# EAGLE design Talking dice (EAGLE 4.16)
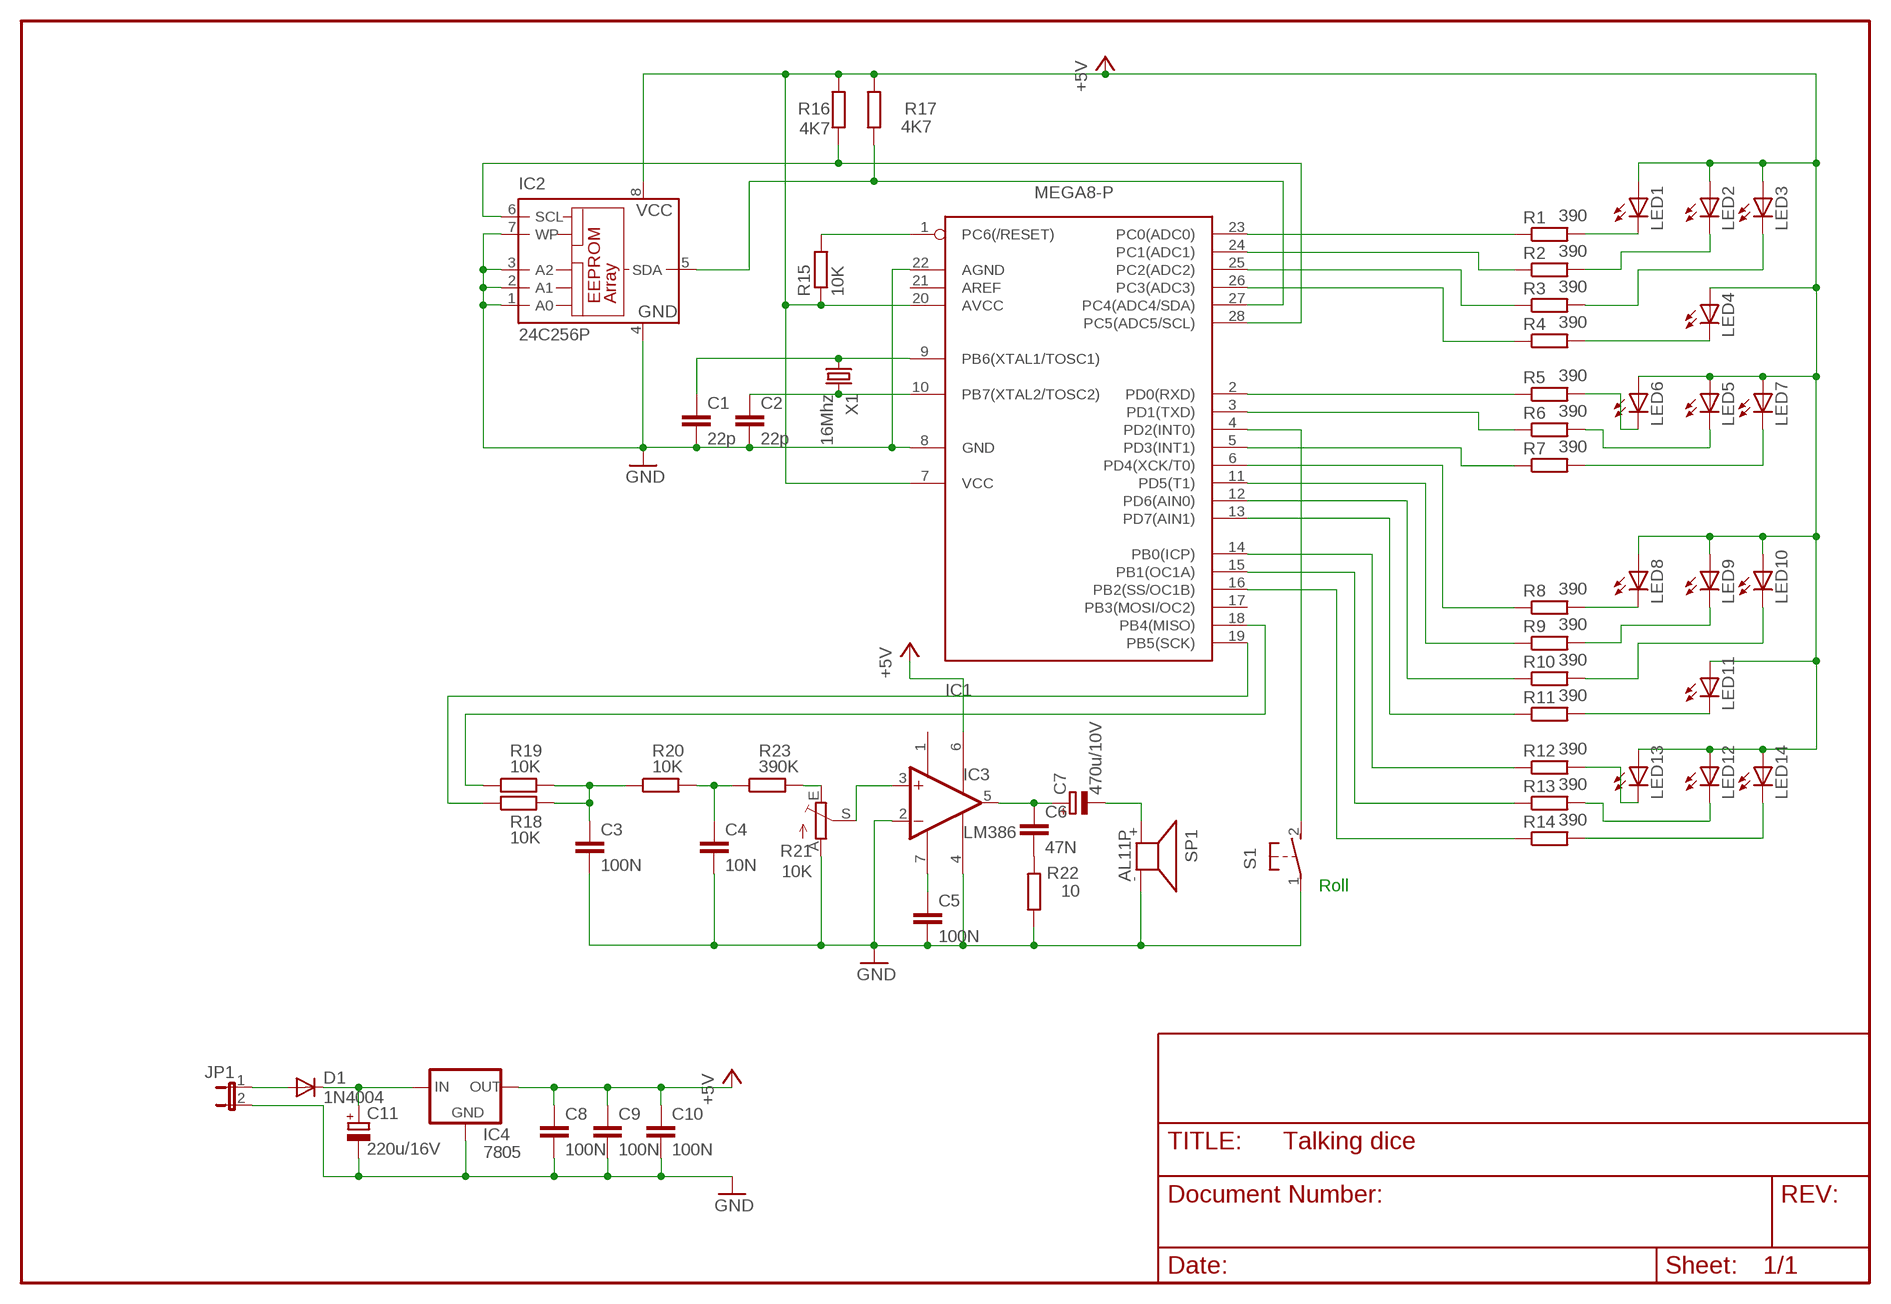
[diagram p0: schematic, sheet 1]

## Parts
C1  22p  C2.5/2  [C2.5-2]
C2  22p  C2.5/2  [C2.5-2]
C3  100N  C2.5/2  [C2.5-2]
C4  10N  C2.5/2  [C2.5-2]
C5  100N  C2.5/2  [C2.5-2]
C6  47N  C2.5/2  [C2.5-2]
C7  470u/10V  CPOL-EUE2,5-6E  [E2,5-6E]
C8  100N  C2.5/2  [C2.5-2]
C9  100N  C2.5/2  [C2.5-2]
C10  100N  C2.5/2  [C2.5-2]
C11  220u/16V  CPOL-EUE2.5-6  [E2,5-6]
D1  1N4004  [DO41-10]
IC1  MEGA8-P  [DIL28-3]
IC2  24C256P  [DIL8]
IC3  LM386  [DIL8]
IC4  7805  78XXS  [78XXS]
JP1  JP1E  [JP1]
LED1  LED5MM  [LED5MM]
LED2  LED5MM  [LED5MM]
LED3  LED5MM  [LED5MM]
LED4  LED5MM  [LED5MM]
LED5  LED5MM  [LED5MM]
LED6  LED5MM  [LED5MM]
LED7  LED5MM  [LED5MM]
LED8  LED5MM  [LED5MM]
LED9  LED5MM  [LED5MM]
LED10  LED5MM  [LED5MM]
LED11  LED5MM  [LED5MM]
LED12  LED5MM  [LED5MM]
LED13  LED5MM  [LED5MM]
LED14  LED5MM  [LED5MM]
R1  390  R-EU_0207/10  [0207/10]
R2  390  R-EU_0207/10  [0207/10]
R3  390  R-EU_0207/10  [0207/10]
R4  390  R-EU_0207/10  [0207/10]
R5  390  R-EU_0207/10  [0207/10]
R6  390  R-EU_0207/10  [0207/10]
R7  390  R-EU_0207/10  [0207/10]
R8  390  R-EU_0207/10  [0207/10]
R9  390  R-EU_0207/10  [0207/10]
R10  390  R-EU_0207/10  [0207/10]
R11  390  R-EU_0207/10  [0207/10]
R12  390  R-EU_0207/10  [0207/10]
R13  390  R-EU_0207/10  [0207/10]
R14  390  R-EU_0207/10  [0207/10]
R15  10K  R-EU_0207/10  [0207/10]
R16  4K7  R-EU_0207/10  [0207/10]
R17  4K7  R-EU_0207/10  [0207/10]
R18  10K  R-EU_0207/10  [0207/10]
R19  10K  R-EU_0207/10  [0207/10]
R20  10K  R-EU_0207/10  [0207/10]
R21  10K  TRIM_EU-ST15  [ST15]
R22  10  R-EU_0207/10  [0207/10]
R23  390K  R-EU_0207/10  [0207/10]
S1  31-XXPIN  [DRUK_PIN]
SP1  AL11P  [AL11P]
X1  16Mhz  CRYTALHC49U-V  [HC49U-V]

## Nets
+5V: C8.1 C9.1 C10.1 IC1.7(VCC) IC1.20(AVCC) IC2.8(VCC) IC3.6 IC4.OUT LED1.A LED2.A LED3.A LED4.A LED5.A LED6.A LED7.A LED8.A LED9.A LED10.A LED11.A LED12.A LED13.A LED14.A R15.1 R16.2 R17.2
GND: C1.2 C2.2 C3.2 C4.2 C5.2 C8.2 C9.2 C10.2 C11.- IC1.8(GND) IC1.22(AGND) IC2.1(A0) IC2.2(A1) IC2.3(A2) IC2.4(GND) IC2.7(WP) IC3.2(-IN) IC3.4 IC4.GND JP1.2 R21.A R22.1 S1.1(P) SP1.-
N$1: LED1.K(C) R1.2
N$2: LED2.K(C) R2.2
N$3: LED3.K(C) R3.2
N$4: C2.1 IC1.10(PB7(XTAL2/TOSC2)) X1.2
N$5: LED4.K(C) R4.2
N$6: IC1.2(PD0(RXD)) R5.1
N$7: LED5.K(C) R6.2
N$8: LED7.K(C) R7.2
N$9: LED6.K(C) R5.2
N$10: IC1.3(PD1(TXD)) R6.1
N$11: LED8.K(C) R8.2
N$12: LED9.K(C) R9.2
N$13: LED10.K(C) R10.2
N$14: C1.1 IC1.9(PB6(XTAL1/TOSC1)) X1.1
N$15: LED11.K(C) R11.2
N$16: LED12.K(C) R13.2
N$17: LED14.K(C) R14.2
N$18: LED13.K(C) R12.2
N$19: IC1.23(PC0(ADC0)) R1.1
N$20: IC1.24(PC1(ADC1)) R2.1
N$21: IC1.25(PC2(ADC2)) R3.1
N$22: IC1.26(PC3(ADC3)) R4.1
N$23: IC1.5(PD3(INT1)) R7.1
N$24: IC1.6(PD4(XCK/T0)) R8.1
N$25: IC1.11(PD5(T1)) R9.1
N$26: IC1.12(PD6(AIN0)) R10.1
N$27: IC1.13(PD7(AIN1)) R11.1
N$28: IC1.14(PB0(ICP)) R12.1
N$29: IC1.15(PB1(OC1A)) R13.1
N$30: IC1.16(PB2(SS/OC1B)) R14.1
N$31: IC1.1(PC6(/RESET)) R15.2
N$32: C3.1 R18.2 R19.2 R20.1
N$33: IC1.27(PC4(ADC4/SDA)) IC2.5(SDA) R17.1
N$34: IC1.28(PC5(ADC5/SCL)) IC2.6(SCL) R16.1
N$35: C4.1 R20.2 R23.1
N$36: IC3.3(+IN) R21.S
N$37: C6.2 R22.2
N$38: C6.1 C7.+ IC3.5(OUT)
N$39: C7.- SP1.+
N$40: IC1.19(PB5(SCK)) R18.1
N$41: IC1.18(PB4(MISO)) R19.1
N$42: C5.1 IC3.7
N$43: D1.A JP1.1
N$44: C11.+ D1.C IC4.IN
N$45: IC1.4(PD2(INT0)) S1.2(S)
N$46: R21.E R23.2
Unconnected: IC1.17(PB3(MOSI/OC2)) IC1.21(AREF) IC3.1

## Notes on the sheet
- Roll

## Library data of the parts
C1-C6 C8-C10 = capacitor-wima:C: CAPACITOR
C7 C11 = rcl:CPOL-EU: POLARIZED CAPACITOR, European symbol
D1 = diode:1N4004: DIODE
IC1 = avr:MEGA8-P: MICROCONTROLLER 8 Kbytes FLASH 1 kbytes SRAM 512 bytes EEPROM USART 4-channel 10 bit ADC 2-channel 8 bit ADC
IC2 = microchip:24C*: Serial EEPROM 1 K/2 K/4 K
IC3 = Evert:LM386: OP AMP
IC4 = v-reg:78XXS: VOLTAGE REGULATOR
JP1 = jumper:JP1E: JUMPER
LED1-LED14 = led:LED: LED
R1-R20 R22 R23 = rcl:R-EU_: RESISTOR, European symbol
R21 = pot:TRIM_EU-: POTENTIOMETER
S1 = Evert:31-XX: OMRON SWITCH
SP1 = Evert:AL11P: SPEAKER
X1 = crystal:CRYTAL: CRYSTAL

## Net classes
0 default: width 0.508 mm, drill 0.127 mm
1 Vcc: width 0.635 mm, drill 0.127 mm
2 Power: width 25 mm, drill 0.127 mm

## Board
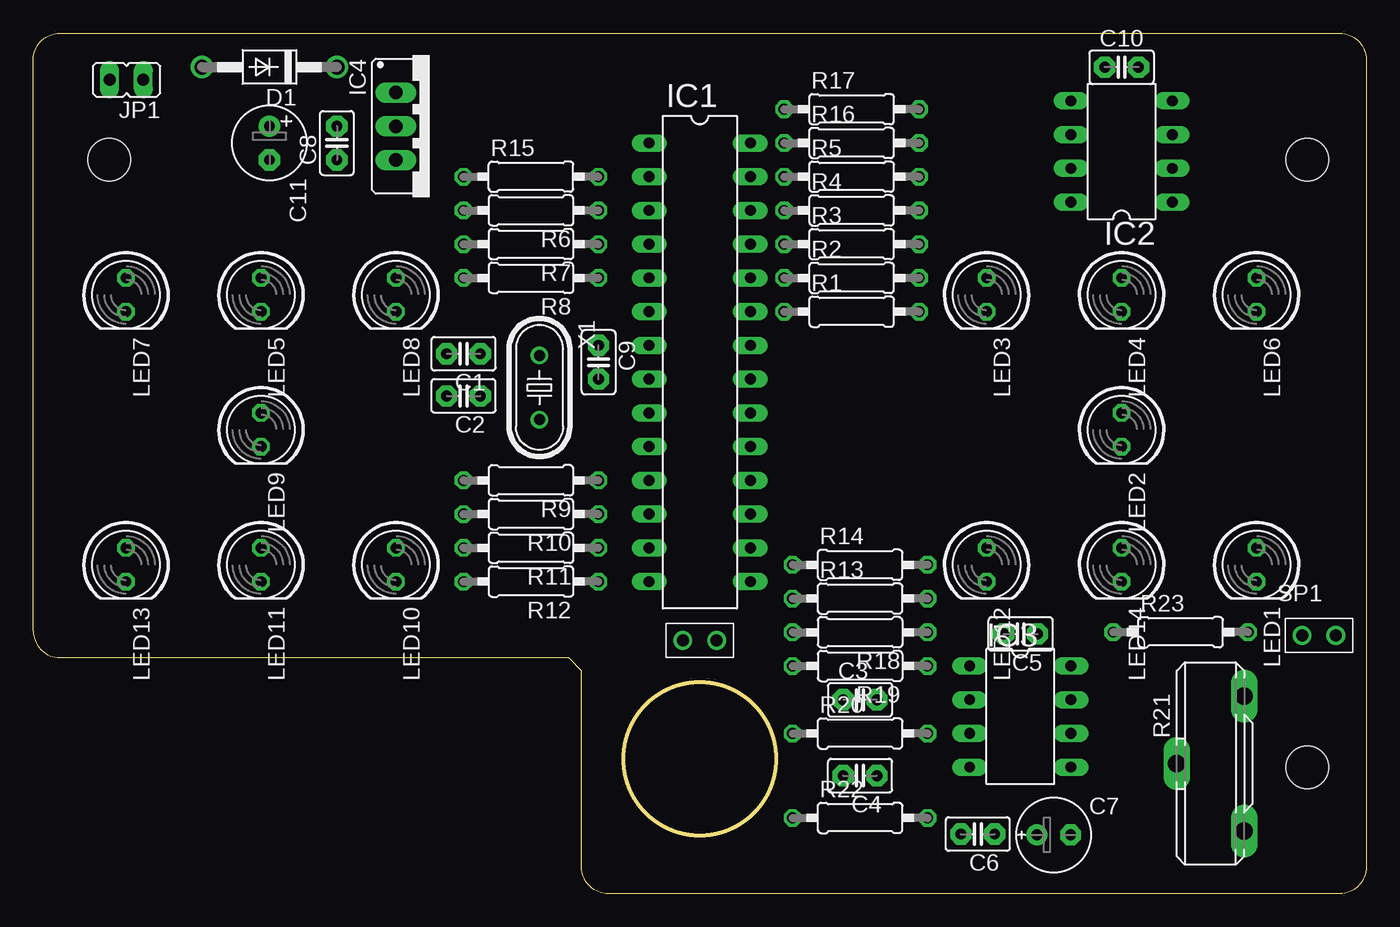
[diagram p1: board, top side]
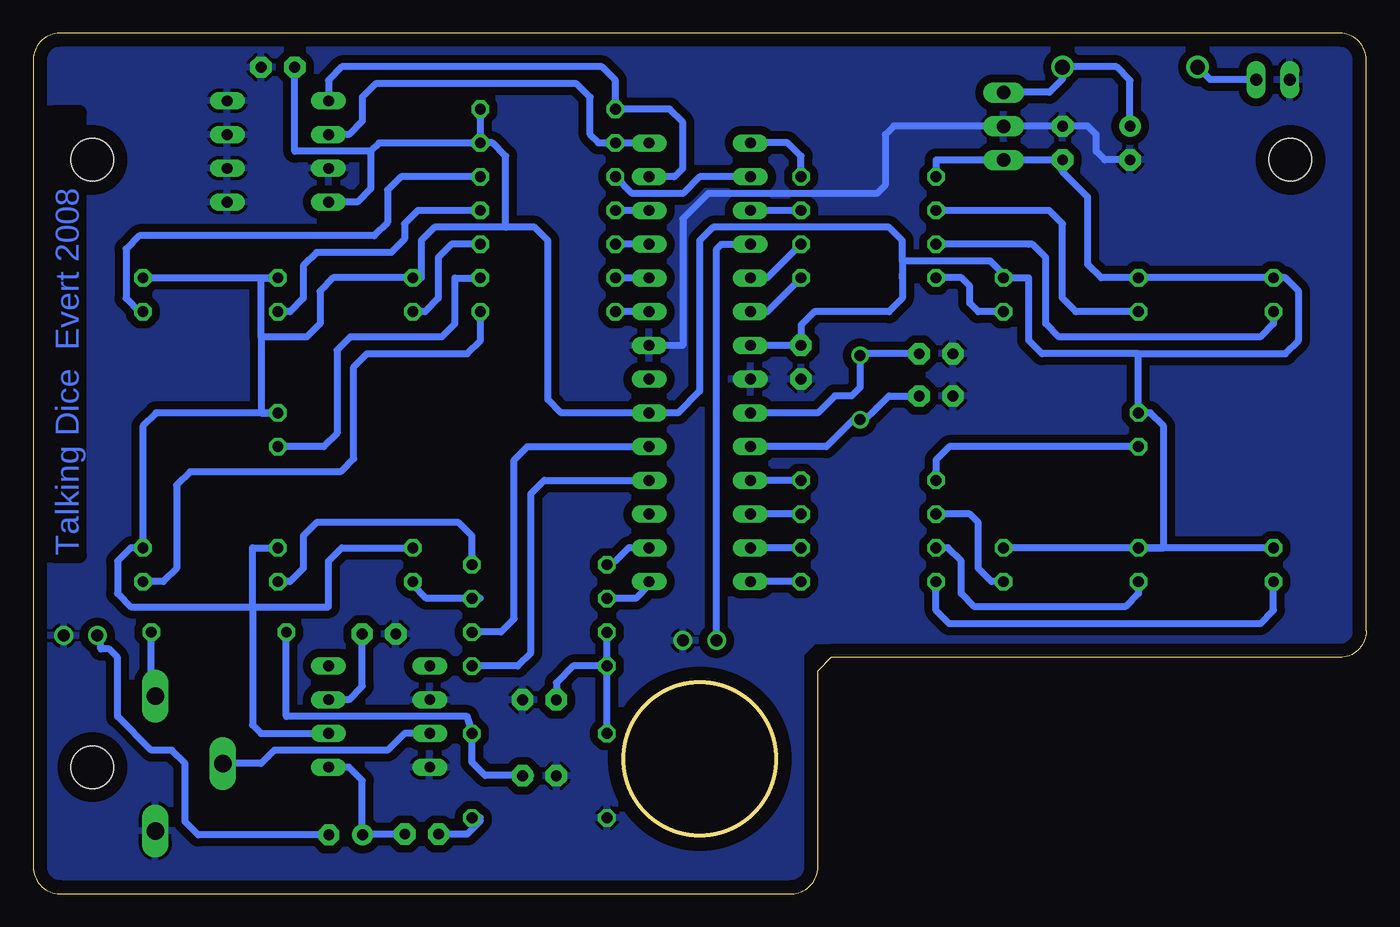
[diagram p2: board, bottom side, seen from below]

Size 100.33 x 64.77 mm. Coordinates in mm from the lower left corner, seen from the top.
Outline: 40.27,17.78 41.27,16.78 41.27,2 arc90 43.27,0 98.33,0 arc90 100.33,2 100.33,62.77 arc90 98.33,64.77 2,64.77 arc90 0,62.77 0,19.78 arc90 2,17.78 40.27,17.78
Outline: circle at 50.16,10.16 radius 5.75
Copper layers (1*16): Top 0.035mm / dielectric 1.5mm / Bottom 0.035mm
Design rules "default": minimum track width 10mil, minimum drill 24mil, track to track 8mil, track to pad 8mil, pad to pad 8mil, via to via 8mil, smd to smd 8mil, copper to edge 40mil, drill to drill 8mil, minimum pad ring 10mil, minimum via ring 8mil, stop-mask expansion 4mil, vias tented up to drill 0mil, thermal gap 10mil
Holes 3.2 mm at 5.71,55.24 95.89,9.52 95.89,55.24

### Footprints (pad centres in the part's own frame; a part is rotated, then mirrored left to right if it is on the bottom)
C2.5-2 = drill 0.813 pad 1.6 octagon: 1 -1.27,0; 2 1.27,0
E2,5-6E = drill 0.813 pad 1.575 round: + -1.27,0 | drill 0.813 pad 1.575 octagon: - 1.27,0
E2,5-6 = drill 0.813 pad 1.6 round: + -1.27,0 | drill 0.813 pad 1.6 octagon: - 1.27,0
DO41-10 = drill 1.118 round: A 5.08,0; C -5.08,0
DIL28-3 = drill 0.813 long: 1 -16.51,-3.81; 2 -13.97,-3.81; 3 -11.43,-3.81; 4 -8.89,-3.81; 5 -6.35,-3.81; 6 -3.81,-3.81; 7 -1.27,-3.81; 8 1.27,-3.81; 9 3.81,-3.81; 10 6.35,-3.81; 11 8.89,-3.81; 12 11.43,-3.81; 13 13.97,-3.81; 14 16.51,-3.81; 15 16.51,3.81; 16 13.97,3.81; 17 11.43,3.81; 18 8.89,3.81; 19 6.35,3.81; 20 3.81,3.81; 21 1.27,3.81; 22 -1.27,3.81; 23 -3.81,3.81; 24 -6.35,3.81; 25 -8.89,3.81; 26 -11.43,3.81; 27 -13.97,3.81; 28 -16.51,3.81
DIL8 = drill 0.813 long: 1 -3.81,-3.81; 2 -1.27,-3.81; 3 1.27,-3.81; 4 3.81,-3.81; 5 3.81,3.81; 6 1.27,3.81; 7 -1.27,3.81; 8 -3.81,3.81
78XXS = drill 1.016 long: GND 0,-2.54; IN -2.54,-2.54; OUT 2.54,-2.54
JP1 = drill 0.914 long: 1 0,-1.27; 2 0,1.27
LED5MM = drill 0.813 octagon: A -1.27,0; K 1.27,0
0207/10 = drill 0.813 octagon: 1 -5.08,0; 2 5.08,0
ST15 = drill 1.321 long: A -5.08,-2.54; E 5.08,-2.54; S 0,2.54
DRUK_PIN = drill 0.9 round: 1 -1.27,0; 2 1.27,0
AL11P = drill 0.9 round: + -1.27,0; - 1.27,0
HC49U-V = drill 0.813 round: 1 -2.413,0; 2 2.413,0

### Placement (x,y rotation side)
C1  32.38,40.64 180 top
C2  32.38,37.46 180 top
C3  62.23,14.6 0 top
C4  62.23,8.88 180 top
C5  74.31,19.55 180 top
C6  71.09,4.49 180 top
C7  76.81,4.42 0 top
C8  22.86,56.5 90 top
C9  42.54,40 270 top
C10  81.92,62.22 0 top
C11  17.78,56.5 270 top
D1  17.78,62.22 180 top
IC1  50.16,40 270 top
IC2  81.92,55.87 90 top
IC3  74.29,13.33 270 top
IC4  29.84,57.77 270 top
JP1  7.02,61.27 90 top
LED1  92.08,24.76 270 top
LED2  81.92,34.92 270 top
LED3  71.76,45.08 270 top
LED4  81.92,45.08 270 top
LED5  17.15,45.08 270 top
LED6  92.08,45.08 270 top
LED7  6.98,45.08 270 top
LED8  27.31,45.08 270 top
LED9  17.15,34.92 270 top
LED10  27.31,24.76 270 top
LED11  17.15,24.76 270 top
LED12  71.76,24.76 270 top
LED13  6.98,24.76 270 top
LED14  81.92,24.76 270 top
R1  61.59,43.81 0 top
R2  61.59,46.35 0 top
R3  61.59,48.89 0 top
R4  61.59,51.43 0 top
R5  61.59,53.97 0 top
R6  37.46,51.43 180 top
R7  37.46,48.89 180 top
R8  37.46,46.35 180 top
R9  37.46,31.11 180 top
R10  37.46,28.57 180 top
R11  37.46,26.03 180 top
R12  37.46,23.49 180 top
R13  62.23,22.21 0 top
R14  62.23,24.76 0 top
R15  37.46,53.97 0 top
R16  61.59,56.51 0 top
R17  61.59,59.05 0 top
R18  62.23,19.68 180 top
R19  62.23,17.14 180 top
R20  62.23,12.05 0 top
R21  88.59,9.8 90 top
R22  62.23,5.7 0 top
R23  86.36,19.69 0 top
S1  50.16,19.06 180 top
SP1  96.77,19.44 0 top
X1  38.1,38.1 270 top

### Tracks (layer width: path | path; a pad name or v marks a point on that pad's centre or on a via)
+5V
  Bottom 0.508: 17.15,40.64 24.4,40.64 25.4,41.64 25.4,46.33 25.43,46.35 LED8.A 27.31,46.62 28.31,47.62 34.92,47.62 | LED9.A 17.15,40.64 | LED11.A 15.24,26.04 15.24,35.19 16.24,36.19 LED9.A | LED10.A LED11.A | LED13.A LED11.A | 17.15,40.64 6.08,40.64 5.08,41.64 5.08,45.35 6.08,46.35 LED7.A | LED7.A | LED7.A LED5.A | 27.3,55.24 27.31,55.24 | IC4.OUT 27.3,55.24 | C8.1 IC4.OUT 27.3,55.24 | IC4.OUT 32.37,55.23 32.38,55.24 R15.1 | IC4.OUT C8.1 22.86,54.34 20.96,52.43 20.96,47.35 19.96,46.35 LED5.A | LED5.A | LED4.A LED6.A | LED4.A 83.19,46.35 83.19,41.91 | LED4.A 83.19,46.35 83.19,41.91 | 83.19,41.91 83.19,36.2 LED2.A 91.08,36.19 92.08,35.19 LED1.A 92.98,26.03 93.98,25.03 93.98,22.59 92.98,21.59 83.82,21.59 | 83.82,21.59 83.82,26.04 LED14.A 83.82,26.03 83.82,21.59 | 83.82,21.59 78.11,21.59 78.11,25.04 77.11,26.04 LED12.A | R16.2 R17.2 | 74.93,55.88 74.3,56.51 R16.2 | IC2.8 78.11,52.07 75.93,52.07 74.93,53.07 74.93,55.88 | C10.1 80.65,55.88 74.93,55.88 | 64.77,50.16 70.12,50.16 71.12,49.16 71.12,46.35 LED3.A 77.74,46.35 78.74,45.35 78.74,42.91 79.74,41.91 83.19,41.91 | 64.77,50.16 64.77,55.52 65.77,56.52 R16.2 | 64.77,50.16 62.59,50.16 61.59,49.16 61.59,37.19 60.59,36.19 IC1.20 51.8,36.19 50.16,37.82 50.16,49.16 49.16,50.16 35.92,50.16 34.92,49.16 34.92,47.62 | 34.92,46.35 34.92,46.62 | 34.92,46.35 34.92,44.81 35.92,43.81 41.54,43.81 42.54,42.81 C9.1 IC1.7 | LED9.A | 34.92,47.62 34.92,46.35 | 83.82,21.59 83.82,12.7 83.19,12.06 IC3.6
GND
  Bottom 0.508: 27.3,57.78 IC4.GND C8.2 20.96,57.78 20.32,57.15 20.32,55.88 19.69,55.24 C11.- | 27.31,57.78 IC4.GND 27.3,57.78 | IC1.22 51.44,41.27 51.43,41.27 51.43,50.8 49.53,52.7 36.83,52.7 36.2,53.34 36.2,57.15 35.56,57.78 27.31,57.78 | 27.3,57.78 27.31,57.78
  pour Bottom (isolate 0.61): 98.7,64.14 99.7,63.13 99.7,1.64 98.7,0.64 44.18,0.64 42.54,1.64 42.54,18.05 41.54,19.05 1.64,19.05 0.64,20.05 0.64,63.13 1.64,64.14
N$1
  Bottom 0.508: R1.2 66.68,41.64 67.68,40.64 75.2,40.64 76.2,39.64 76.2,32.75 77.2,31.75 88.54,31.75 89.54,30.75 89.54,24.5 90.54,23.5 LED1.K
N$2
  Bottom 0.508: R2.2 68.58,46.35 68.58,42.91 69.58,41.91 76.47,41.91 77.47,40.91 77.47,34.66 78.47,33.66 LED2.K
N$3
  Bottom 0.508: LED3.K 70.85,43.81 69.85,44.81 69.85,47.89 68.85,48.89 R3.2
N$4
  Bottom 0.406: 38.1,35.56 X1.2 38.61,35.69 | IC1.10
  Bottom 0.508: 38.1,35.56 37.83,35.56 36.83,36.56 35.92,37.46 C2.1 | 38.61,35.69 40,34.29 40.64,33.66 IC1.10
N$5
  Bottom 0.508: R4.2 71.39,51.43 72.39,50.43 72.39,49.26 73.39,48.26 79.01,48.26 80.01,47.26 80.01,44.81 81.01,43.81 LED4.K
N$6
  Bottom 0.508: IC1.2 50.17,53.97 51.43,52.7 55.24,52.7 R5.1
N$7
  Bottom 0.508: R6.2 24.14,51.43 23.86,51.43 22.86,50.43 22.86,44.81 21.86,43.81 LED5.K
N$8
  Bottom 0.508: R7.2 25.41,48.89 25.13,48.89 24.13,47.89 24.13,42.91 23.13,41.91 7.98,41.91 6.98,42.91 LED7.K
N$9
  Bottom 0.508: R5.2 72.66,53.97 73.66,52.97 73.66,50.53 74.66,49.53 92.34,49.53 93.34,48.53 93.34,44.81 92.34,43.81 LED6.K
N$10
  Bottom 0.508: R6.1 42.71,51.43 | 42.71,51.43 IC1.3 | 42.71,51.43 42.71,51.63
N$11
  Bottom 0.508: LED8.K 29.21,43.81 29.85,44.45 29.85,45.72 30.48,46.35 R8.2
N$12
  Bottom 0.508: LED9.K 31.39,33.65 32.38,32.65 R9.2
N$13
  Bottom 0.508: R10.2 29.85,28.57 29.21,27.94 29.21,24.5 28.21,23.5 LED10.K
N$14
  Bottom 0.406: 38.1,40.64 X1.1 | IC1.9
  Bottom 0.508: C1.1 38.1,40.64 | X1.1 38.1,38.1 38.73,37.46 40,37.46 41.27,36.2 IC1.9
N$15
  Bottom 0.508: LED11.K 17.15,22.59 18.15,21.59 29.48,21.59 30.48,22.59 30.48,25.03 31.48,26.03 R11.2
N$16
  Bottom 0.508: R13.2 66.68,22.23 70.76,22.23 71.76,23.23 LED12.K
N$17
  Bottom 0.508: R14.2 67.31,26.94 68.31,27.94 79.01,27.94 80.01,26.94 80.01,24.5 81.01,23.5 LED14.K
N$18
  Bottom 0.508: LED13.K 6.98,21.32 7.98,20.32 31.39,20.32 32.38,21.32 R12.2
N$19
  Bottom 0.508: IC1.23 R1.1
N$20
  Bottom 0.508: IC1.24 R2.1
N$21
  Bottom 0.508: IC1.25 R3.1
N$22
  Bottom 0.508: IC1.26 R4.1
N$23
  Bottom 0.508: R7.1 42.71,48.89 | 42.71,48.89 42.71,49.09 | 42.71,48.89 42.71,48.73 45.09,46.35 IC1.5
N$24
  Bottom 0.508: R8.1 42.71,46.35 | 42.71,46.35 42.71,46.53 | 42.71,46.35 42.71,46.19 45.09,43.81 IC1.6
N$25
  Bottom 0.508: R9.1 IC1.11
N$26
  Bottom 0.508: R10.1 IC1.12
N$27
  Bottom 0.508: R11.1 IC1.13
N$28
  Bottom 0.508: IC1.14 R12.1
N$29
  Bottom 0.508: R13.1 56.52,22.23 54.98,22.23 53.98,23.23 IC1.15
N$30
  Bottom 0.508: IC1.16 55.52,26.03 56.52,25.03 R14.1
N$31
  Bottom 0.508: IC1.1 43.54,56.52 42.54,55.52 R15.2
N$32
  Bottom 0.508: R20.1 R19.2 | R19.2 R18.2 | R19.2 59.7,17.14 60.96,15.88 C3.1
N$33
  Bottom 0.508: IC2.5 78.11,61.23 77.11,62.23 57.52,62.23 56.52,61.23 R17.1 52.43,59.05 51.43,58.05 51.43,54.61 52.07,53.97 IC1.27
N$34
  Bottom 0.508: IC1.28 R16.1 57.78,56.51 57.78,56.52 58.42,57.15 58.42,59.96 59.42,60.96 74.57,60.96 75.57,59.96 75.57,58.15 76.57,57.15 78.11,57.15 IC2.6
N$35
  Bottom 0.508: C4.1 62.86,8.89 66.31,8.89 67.31,9.89 R20.2 67.31,12.33 67.68,13.33 81.28,13.33 R23.1
N$36
  Bottom 0.508: R21.S 83.19,9.8 82.19,10.79 73.66,10.79 72.39,12.06 IC3.3
N$37
  Bottom 0.508: 66.68,5.71 R22.2 66.68,5.48 67.68,4.49 C6.2
N$38
  Bottom 0.508: C6.1 75.57,4.49 75.57,4.42 | 75.57,4.42 C7.+ | IC3.5 76.57,9.53 75.57,8.53 75.57,4.42
N$39
  Bottom 0.508: C7.- 87.9,4.42 88.9,5.42 88.9,9.79 89.9,10.79 91.44,10.79 93.98,13.33 93.98,17.78 94.62,18.42 95.25,18.42 95.25,19.69 SP1.+
N$40
  Bottom 0.508: R18.1 66.68,19.69 65.14,19.69 64.14,20.69 64.14,32.65 63.13,33.65 IC1.19
N$41
  Bottom 0.508: R19.1 63.86,17.14 62.86,18.14 62.86,30.12 61.86,31.12 IC1.18
N$42
  Bottom 0.508: C5.1 75.57,19.55 75.57,15.61 76.57,14.61 IC3.7
N$43
  Bottom 0.508: D1.A | D1.A | JP1.1 11.75,61.27 D1.A
N$44
  Bottom 0.508: C11.+ 17.78,61.23 18.78,62.23 D1.C | D1.C | IC4.IN 27.31,60.32 23.86,60.32 22.86,61.32 D1.C
N$45
  Bottom 0.508: IC1.4 48.53,48.89 48.89,48.52 S1.2
N$46
  Bottom 0.406: R21.E 91.08,14.88
  Bottom 0.508: 90.81,14.61 91.08,14.88 91.44,15.24 R23.2

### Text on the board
Bottom: Talking Dice Evert 2008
